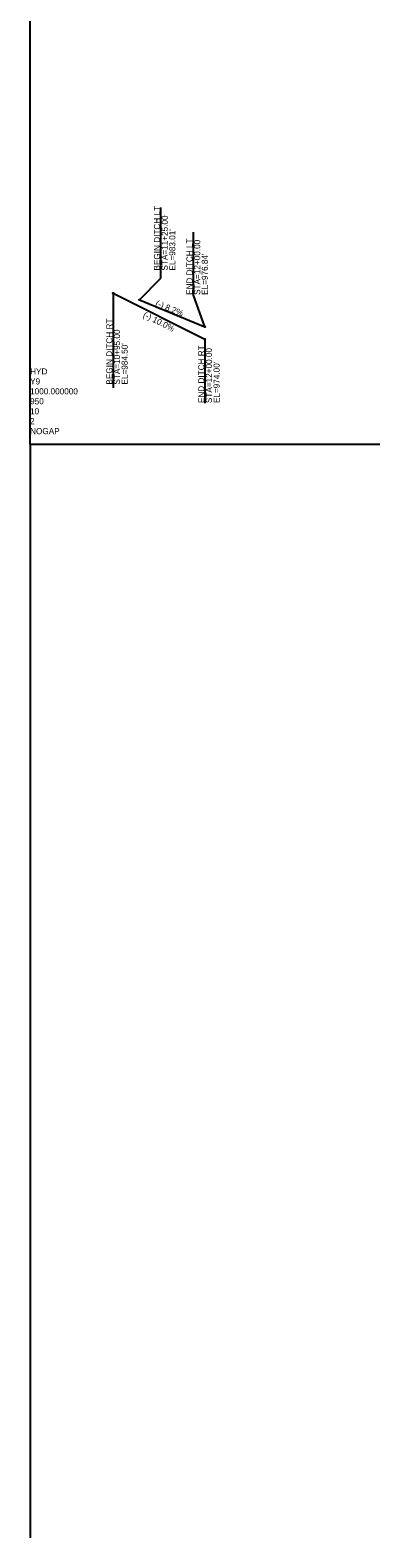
# Model space of a CAD drawing. Extents: x 1623530 to 1630103, y 894455 to 902584.
# Drawn here: x 1626639 to 1627039, y 894455 to 896178 of the extents above; entities that cross this region are included whole.
import ezdxf

# ---------------------------------------------------------------- set-up
doc = ezdxf.new("R2010")
doc.units = 0
for name, color, linetype in [('Exist Profile Cell', 7, 'Continuous'), ('Prop Vertical Profile Ditch Grade Left', 7, 'Continuous'), ('Prop Vertical Profile Ditch Grade Left Label', 7, 'Continuous'), ('Prop Vertical Profile Ditch Grade Right', 7, 'Continuous'), ('Prop Vertical Profile Ditch Grade Right Label', 7, 'Continuous'), ('Prop VPI Ditch Grade Right Label', 7, 'Continuous')]:
    doc.layers.add(name, color=color, linetype=linetype)

msp = doc.modelspace()

# ---------------------------------------------------------------- linework, layer by layer
at = {"layer": 'Exist Profile Cell'}
for q in [(1626639, 896954.7), (1627039, 895704.7), (1626639, 894454.7)]:
    msp.add_line((1626639, 895704.7), q, dxfattribs=at)
at = {"layer": 'Prop Vertical Profile Ditch Grade Left'}
msp.add_line((1626764, 895869.7), (1626839, 895838.9), dxfattribs=at)
for centre in [(1626764, 895869.7), (1626839, 895838.9)]:
    msp.add_circle(centre, 0.5, dxfattribs=at)
at = {"layer": 'Prop Vertical Profile Ditch Grade Left Label'}
for p, q in [((1626788.6, 895894.4), (1626788.6, 895975.3)), ((1626826, 895875.1), (1626826, 895946.8)), ((1626764, 895869.7), (1626788.6, 895894.4)), ((1626839, 895838.9), (1626826, 895875.1))]:
    msp.add_line(p, q, dxfattribs=at)
at = {"layer": 'Prop Vertical Profile Ditch Grade Right'}
msp.add_line((1626734, 895877.2), (1626839, 895824.7), dxfattribs=at)
at = {"layer": 'Prop VPI Ditch Grade Right Label'}
for p, q in [((1626734, 895877.2), (1626734, 895769.2)), ((1626839, 895824.7), (1626839, 895751.6))]:
    msp.add_line(p, q, dxfattribs=at)
for centre in [(1626734, 895877.2), (1626839, 895824.7)]:
    msp.add_circle(centre, 0.5, dxfattribs=at)

# ---------------------------------------------------------------- texts
at = {"layer": 'Exist Profile Cell'}
for s, p in [('HYD', (1626639, 895784.3)), ('Y9', (1626639, 895772.9)), ('1000.000000', (1626639, 895761.6)), ('950', (1626639, 895750.2)), ('2', (1626639, 895727.4)), ('10', (1626639, 895738.8)), ('NOGAP', (1626639, 895716.1))]:
    msp.add_text(s, height=7, dxfattribs=at).set_placement(p)
at = {"layer": 'Prop Vertical Profile Ditch Grade Left'}
for s, rotation, p in [('BEGIN DITCH LT', 90, (1626787.6, 895903.1)), ('STA=11+25.00', 90, (1626796.4, 895903.1)), ("EL=983.01'", 90, (1626805.1, 895903.1)), ('END DITCH LT', 90, (1626824.8, 895875.3)), ('STA=12+00.00', 90, (1626833.6, 895875.3)), ("EL=976.84'", 90, (1626842.3, 895875.3)), ('(-) 8.2%', 337.641, (1626781.7, 895863.1))]:
    msp.add_text(s, height=7, rotation=rotation, dxfattribs=at).set_placement(p)
at = {"layer": 'Prop Vertical Profile Ditch Grade Right Label'}
msp.add_text('(-) 10.0%', height=7, rotation=333.4349, dxfattribs=at).set_placement((1626767.5, 895850.2))
at = {"layer": 'Prop VPI Ditch Grade Right Label'}
for s, p in [('BEGIN DITCH RT', (1626733.1, 895772.8)), ('STA=10+95.00', (1626741.8, 895772.8)), ("EL=984.50'", (1626750.6, 895772.8)), ('END DITCH RT', (1626838.3, 895751.6)), ('STA=12+00.00', (1626847, 895751.6)), ("EL=974.00'", (1626855.8, 895751.6))]:
    msp.add_text(s, height=7, rotation=90, dxfattribs=at).set_placement(p)

doc.saveas('drawing.dxf')
